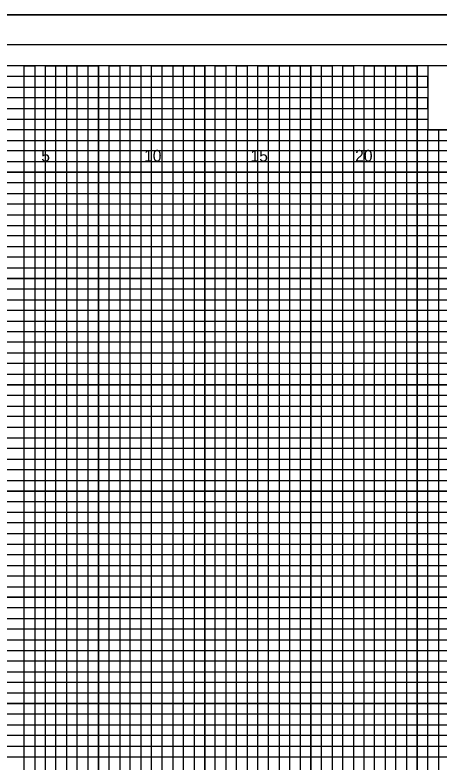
# Model space of a CAD drawing. Extents: x -4 to 103, y -2 to 209.
# Drawn here: x 54.82 to 74.78, y 103.08 to 138.22 of the extents above; entities that cross this region are included whole.
import ezdxf

# ---------------------------------------------------------------- set-up
doc = ezdxf.new("R2010")
doc.units = 0
for name, color, linetype in [('Exist XS Ground Line', 7, 'Continuous'), ('Old_Level_10', 7, 'Continuous'), ('Old_Level_16', 7, 'Continuous'), ('Old_Level_3', 7, 'Continuous'), ('Old_Level_5', 7, 'Continuous'), ('Old_Level_8', 7, 'Continuous'), ('Prop XS Finish Grade Earthwork', 7, 'Continuous'), ('Prop XS SE Text', 7, 'Continuous')]:
    doc.layers.add(name, color=color, linetype=linetype)

msp = doc.modelspace()

# ---------------------------------------------------------------- linework, layer by layer
at = {"layer": 'Exist XS Ground Line'}
msp.add_lwpolyline([(103, 136.825), (-2.8, 136.825), (-2.8, 69.825), (103, 69.825)], close=True, dxfattribs=at)
at = {"layer": 'Old_Level_10'}
for p, q in [((56.25, 70.825), (56.25, 135.825)), ((58.75, 70.825), (58.75, 135.825)), ((61.25, 70.825), (61.25, 135.825)), ((63.75, 70.825), (63.75, 135.825)), ((66.25, 70.825), (66.25, 135.825)), ((68.75, 70.825), (68.75, 135.825)), ((71.25, 70.825), (71.25, 135.825)), ((73.75, 70.825), (73.75, 135.825)), ((0, 133.325), (74.25, 133.325)), ((0, 130.825), (102.5, 130.825)), ((0, 128.325), (102.5, 128.325)), ((0, 125.825), (102.5, 125.825)), ((0, 123.325), (102.5, 123.325)), ((0, 120.825), (102.5, 120.825)), ((0, 118.325), (102.5, 118.325)), ((0, 115.825), (102.5, 115.825)), ((0, 113.325), (102.5, 113.325)), ((0, 110.825), (102.5, 110.825)), ((0, 108.325), (102.5, 108.325)), ((0, 105.825), (102.5, 105.825)), ((0, 103.325), (102.5, 103.325))]:
    msp.add_line(p, q, dxfattribs=at)
at = {"layer": 'Old_Level_3'}
msp.add_line((-3.5, 138.225), (103.4, 138.225), dxfattribs=at)
at = {"layer": 'Old_Level_5'}
msp.add_lwpolyline([(103.4, 138.225), (-3.5, 138.225), (-3.5, 68.4), (103.4, 68.4)], close=True, dxfattribs=at)
at = {"layer": 'Old_Level_8'}
for points in [[(56.25, 70.825), (56.25, 135.825), (58.75, 135.825), (58.75, 70.825)], [(61.25, 70.825), (61.25, 135.825), (63.75, 135.825), (63.75, 70.825)], [(66.25, 70.825), (66.25, 135.825), (68.75, 135.825), (68.75, 70.825)], [(71.25, 70.825), (71.25, 135.825), (73.75, 135.825), (73.75, 70.825)], [(0, 133.325), (74.25, 133.325)], [(0, 128.325), (102.5, 128.325), (102.5, 130.825), (0, 130.825)], [(0, 123.325), (102.5, 123.325), (102.5, 125.825), (0, 125.825)], [(0, 118.325), (102.5, 118.325), (102.5, 120.825), (0, 120.825)], [(0, 113.325), (102.5, 113.325), (102.5, 115.825), (0, 115.825)], [(0, 108.325), (102.5, 108.325), (102.5, 110.825), (0, 110.825)], [(0, 103.325), (102.5, 103.325), (102.5, 105.825), (0, 105.825)]]:
    msp.add_lwpolyline(points, dxfattribs=at)
at = {"layer": 'Prop XS Finish Grade Earthwork'}
for points in [[(55.25, 70.825), (55.25, 135.825), (55.75, 135.825), (55.75, 70.825)], [(56.75, 70.825), (56.75, 135.825), (57.25, 135.825), (57.25, 70.825)], [(57.75, 70.825), (57.75, 135.825), (58.25, 135.825), (58.25, 70.825)], [(59.25, 70.825), (59.25, 135.825), (59.75, 135.825), (59.75, 70.825)], [(60.25, 70.825), (60.25, 135.825), (60.75, 135.825), (60.75, 70.825)], [(61.75, 70.825), (61.75, 135.825), (62.25, 135.825), (62.25, 70.825)], [(62.75, 70.825), (62.75, 135.825), (63.25, 135.825), (63.25, 70.825)], [(64.25, 70.825), (64.25, 135.825), (64.75, 135.825), (64.75, 70.825)], [(65.25, 70.825), (65.25, 135.825), (65.75, 135.825), (65.75, 70.825)], [(66.75, 70.825), (66.75, 135.825), (67.25, 135.825), (67.25, 70.825)], [(67.75, 70.825), (67.75, 135.825), (68.25, 135.825), (68.25, 70.825)], [(69.25, 70.825), (69.25, 135.825)], [(69.25, 135.825), (69.75, 135.825), (69.75, 70.825)], [(70.25, 70.825), (70.25, 135.825), (70.75, 135.825), (70.75, 70.825)], [(71.75, 70.825), (71.75, 135.825), (72.25, 135.825), (72.25, 70.825)], [(72.75, 70.825), (72.75, 135.825), (73.25, 135.825), (73.25, 70.825)], [(0, 132.825), (0, 133.825), (74.25, 133.825), (74.25, 134.325), (0, 134.325), (0, 134.825), (74.25, 134.825), (74.25, 135.325), (0, 135.325)], [(0, 132.325), (102.5, 132.325), (102.5, 132.825), (0, 132.825)], [(74.25, 70.825), (74.25, 132.825), (74.75, 132.825), (74.75, 70.825)], [(0, 131.325), (102.5, 131.325), (102.5, 131.825), (0, 131.825)], [(0, 129.825), (102.5, 129.825), (102.5, 130.325), (0, 130.325)], [(0, 128.825), (102.5, 128.825), (102.5, 129.325), (0, 129.325)], [(0, 127.325), (102.5, 127.325), (102.5, 127.825), (0, 127.825)], [(0, 126.325), (102.5, 126.325), (102.5, 126.825), (0, 126.825)], [(0, 124.825), (102.5, 124.825), (102.5, 125.325), (0, 125.325)], [(0, 123.825), (102.5, 123.825), (102.5, 124.325), (0, 124.325)], [(0, 122.325), (102.5, 122.325), (102.5, 122.825), (0, 122.825)], [(0, 121.325), (102.5, 121.325), (102.5, 121.825), (0, 121.825)], [(0, 119.825), (102.5, 119.825), (102.5, 120.325), (0, 120.325)], [(0, 118.825), (102.5, 118.825), (102.5, 119.325), (0, 119.325)], [(0, 117.325), (102.5, 117.325), (102.5, 117.825), (0, 117.825)], [(0, 116.325), (102.5, 116.325), (102.5, 116.825), (0, 116.825)], [(0, 114.825), (102.5, 114.825), (102.5, 115.325), (0, 115.325)], [(0, 113.825), (102.5, 113.825), (102.5, 114.325), (0, 114.325)], [(0, 112.325), (102.5, 112.325), (102.5, 112.825), (0, 112.825)], [(0, 111.325), (102.5, 111.325), (102.5, 111.825), (0, 111.825)], [(0, 109.825), (102.5, 109.825), (102.5, 110.325), (0, 110.325)], [(0, 108.825), (102.5, 108.825), (102.5, 109.325), (0, 109.325)], [(0, 107.325), (102.5, 107.325), (102.5, 107.825), (0, 107.825)], [(0, 106.325), (102.5, 106.325), (102.5, 106.825), (0, 106.825)], [(0, 104.825), (102.5, 104.825), (102.5, 105.325), (0, 105.325)], [(0, 103.825), (102.5, 103.825), (102.5, 104.325), (0, 104.325)]]:
    msp.add_lwpolyline(points, dxfattribs=at)
at = {"layer": 'Prop XS SE Text'}
for points in [[(102.5, 135.825), (0, 135.825), (0, 70.825), (102.5, 70.825)], [(83.75, 135.825), (74.25, 135.825), (74.25, 132.825), (83.75, 132.825)]]:
    msp.add_lwpolyline(points, close=True, dxfattribs=at)

# ---------------------------------------------------------------- texts
at = {"layer": 'Old_Level_16'}
for s, p in [('5', (56.057, 131.325)), ('10', (60.897, 131.325)), ('15', (65.906, 131.325)), ('20', (70.831, 131.325))]:
    msp.add_text(s, height=0.55, dxfattribs=at).set_placement(p)

doc.saveas('drawing.dxf')
